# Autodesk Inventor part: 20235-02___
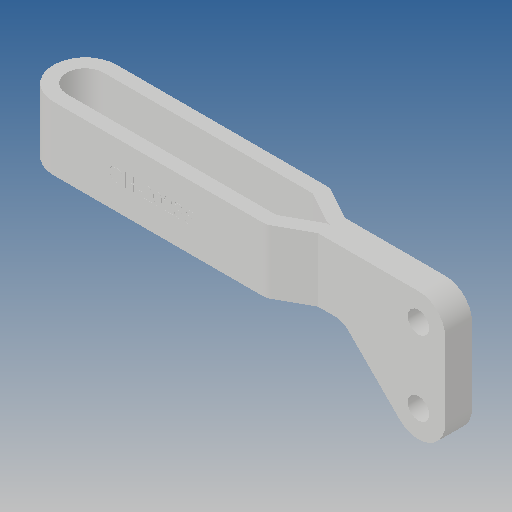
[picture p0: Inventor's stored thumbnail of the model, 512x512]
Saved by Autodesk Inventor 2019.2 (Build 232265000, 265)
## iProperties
Created: 2010-06
Part Number: 20235-02___
Material: Ogólny
Document SubType Name: Modeling
Designer: CADENGINEERING4
Density: 1 g/cm^3
Appearance: Domyślna
Author: CADENGINEERING4
Revision Number: ANY
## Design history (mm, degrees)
feature "NONE"
node "Bryła1"
